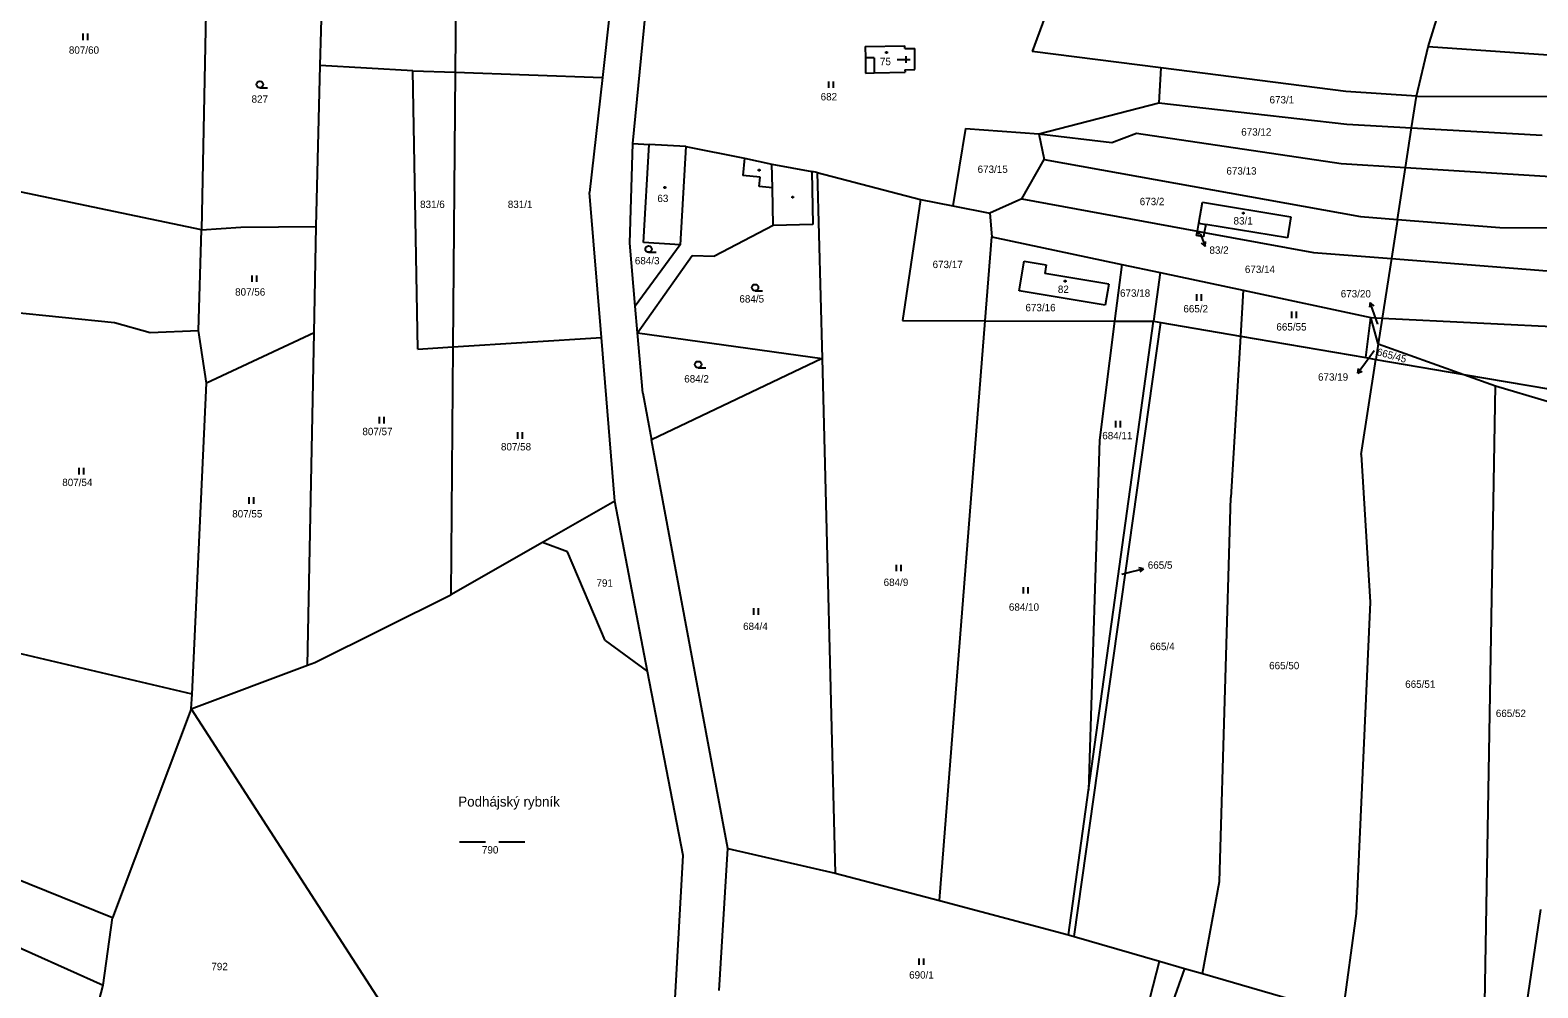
# Model space of a CAD drawing. Extents: x -791032 to -787751, y -1106872 to -1104403.
# Drawn here: x -789685.4 to -789337.7, y -1105820.2 to -1105599.2 of the extents above; entities that cross this region are included whole.
import ezdxf

# ---------------------------------------------------------------- set-up
doc = ezdxf.new("R2010")
doc.units = 0
for name, color, linetype in [('Komunikace', 7, 'Continuous'), ('Vrstva 1', 7, 'Continuous'), ('Vrstva 14', 7, 'Continuous'), ('Vrstva 15', 7, 'Continuous'), ('Vrstva 16', 7, 'Continuous'), ('Vrstva 2', 7, 'Continuous'), ('Vrstva 23', 7, 'Continuous'), ('Vrstva 25', 7, 'Continuous'), ('Vrstva 44', 7, 'Continuous')]:
    doc.layers.add(name, color=color, linetype=linetype)

msp = doc.modelspace()

# ---------------------------------------------------------------- linework, layer by layer
at = {"layer": 'Komunikace'}
for p, q in [((-789415.55, -1105646.15), (-789415.5, -1105646.28)), ((-789374.6, -1105667.04), (-789375.38, -1105664.84)), ((-789375.46, -1105673.21), (-789377.48, -1105675.95)), ((-789433.69, -1105724.75), (-789431.59, -1105724.22))]:
    msp.add_line(p, q, dxfattribs=at)
at = {"layer": 'Vrstva 1'}
for p, q in [((-789644.61, -1105581.09), (-789645.89, -1105645.25)), ((-789618.51, -1105607.33), (-789617.87, -1105582.98)), ((-789363.03, -1105603.06), (-789358.76, -1105589.25)), ((-789587.28, -1105591.81), (-789587.42, -1105608.89)), ((-789551.71, -1105594.77), (-789553.43, -1105610.08)), ((-789546.46, -1105625.33), (-789543.24, -1105592.17)), ((-789451.39, -1105596.16), (-789454.37, -1105604.11)), ((-789492.84, -1105602.94), (-789483.73, -1105602.81)), ((-789492.84, -1105602.94), (-789492.8, -1105605.59)), ((-789483.73, -1105603.41), (-789483.73, -1105602.81)), ((-789483.73, -1105603.41), (-789481.42, -1105603.44)), ((-789481.42, -1105608.24), (-789481.42, -1105603.44)), ((-789424.7, -1105607.88), (-789454.37, -1105604.11)), ((-789365.73, -1105614.42), (-789363.03, -1105603.06)), ((-789311.55, -1105606.53), (-789363.03, -1105603.06)), ((-789619.48, -1105644.48), (-789618.51, -1105607.33)), ((-789597.18, -1105608.55), (-789618.51, -1105607.33)), ((-789597.18, -1105608.55), (-789587.42, -1105608.89)), ((-789596.01, -1105672.81), (-789597.18, -1105608.55)), ((-789587.42, -1105608.89), (-789587.93, -1105672.29)), ((-789587.42, -1105608.89), (-789553.43, -1105610.08)), ((-789492.8, -1105605.59), (-789492.74, -1105609.09)), ((-789490.74, -1105609.05), (-789483.63, -1105608.9)), ((-789483.68, -1105608.31), (-789481.42, -1105608.24)), ((-789483.68, -1105608.31), (-789483.63, -1105608.9)), ((-789424.7, -1105607.88), (-789425.13, -1105615.94)), ((-789381.97, -1105613.32), (-789424.7, -1105607.88)), ((-789553.43, -1105610.08), (-789556.42, -1105636.65)), ((-789492.74, -1105609.09), (-789490.74, -1105609.05)), ((-789452.81, -1105623.11), (-789425.13, -1105615.94)), ((-789425.13, -1105615.94), (-789381.74, -1105620.9)), ((-789365.73, -1105614.42), (-789381.97, -1105613.32)), ((-789366.86, -1105621.73), (-789365.73, -1105614.42)), ((-789365.73, -1105614.42), (-789331.78, -1105614.45)), ((-789469.73, -1105621.91), (-789472.66, -1105639.71)), ((-789469.73, -1105621.91), (-789452.81, -1105623.11)), ((-789381.74, -1105620.9), (-789366.86, -1105621.73)), ((-789368.27, -1105630.86), (-789366.86, -1105621.73)), ((-789366.86, -1105621.73), (-789336.75, -1105623.41)), ((-789547.12, -1105648.3), (-789546.46, -1105625.33)), ((-789546.46, -1105625.33), (-789542.67, -1105625.55)), ((-789543.99, -1105648.21), (-789542.67, -1105625.55)), ((-789534.18, -1105626.04), (-789542.67, -1105625.55)), ((-789534.18, -1105626.04), (-789520.66, -1105628.73)), ((-789452.81, -1105623.11), (-789451.57, -1105629.03)), ((-789452.81, -1105623.11), (-789435.93, -1105625.13)), ((-789435.93, -1105625.13), (-789430.25, -1105622.93)), ((-789430.25, -1105622.93), (-789383.08, -1105629.95)), ((-789520.66, -1105628.73), (-789514.37, -1105630.09)), ((-789456.72, -1105638.1), (-789451.57, -1105629.03)), ((-789451.57, -1105629.03), (-789378.65, -1105642.16)), ((-789514.37, -1105630.09), (-789505.16, -1105631.82)), ((-789505.16, -1105631.82), (-789504.89, -1105644.03)), ((-789503.92, -1105632.05), (-789505.16, -1105631.82)), ((-789503.92, -1105632.05), (-789502.8, -1105674.96)), ((-789503.92, -1105632.05), (-789480.08, -1105638.25)), ((-789383.08, -1105629.95), (-789368.27, -1105630.86)), ((-789370.11, -1105642.84), (-789368.27, -1105630.86)), ((-789368.27, -1105630.86), (-789329.43, -1105633.26)), ((-789645.89, -1105645.25), (-789689.22, -1105636.15)), ((-789553.69, -1105670.1), (-789556.42, -1105636.65)), ((-789480.08, -1105638.25), (-789484.26, -1105666.21)), ((-789480.08, -1105638.25), (-789472.66, -1105639.71)), ((-789472.66, -1105639.71), (-789464.11, -1105641.39)), ((-789456.72, -1105638.1), (-789464.11, -1105641.39)), ((-789456.72, -1105638.1), (-789416.22, -1105645.56)), ((-789415.89, -1105643.74), (-789415.07, -1105638.91)), ((-789415.07, -1105638.91), (-789394.67, -1105642.28)), ((-789464.11, -1105641.39), (-789463.63, -1105646.85)), ((-789416.22, -1105645.56), (-789415.89, -1105643.74)), ((-789394.67, -1105642.28), (-789395.49, -1105647.11)), ((-789378.65, -1105642.16), (-789370.11, -1105642.84)), ((-789370.11, -1105642.84), (-789371.5, -1105651.89)), ((-789370.11, -1105642.84), (-789346.51, -1105644.71)), ((-789646.63, -1105668.52), (-789645.89, -1105645.25)), ((-789645.89, -1105645.25), (-789636.82, -1105644.66)), ((-789636.82, -1105644.66), (-789619.48, -1105644.48)), ((-789619.95, -1105669.06), (-789619.48, -1105644.48)), ((-789514.06, -1105644.23), (-789527.63, -1105651.37)), ((-789504.89, -1105644.03), (-789514.06, -1105644.23)), ((-789465.16, -1105666.26), (-789463.63, -1105646.85)), ((-789463.63, -1105646.85), (-789433.69, -1105653.23)), ((-789416.41, -1105646.59), (-789416.22, -1105645.56)), ((-789414.84, -1105646.88), (-789416.41, -1105646.59)), ((-789416.22, -1105645.56), (-789414.65, -1105645.85)), ((-789414.65, -1105645.85), (-789414.84, -1105646.88)), ((-789414.31, -1105644.03), (-789414.65, -1105645.85)), ((-789414.65, -1105645.85), (-789389.43, -1105650.49)), ((-789395.49, -1105647.11), (-789414.31, -1105644.03)), ((-789346.51, -1105644.71), (-789318.57, -1105644.88)), ((-789545.87, -1105662.9), (-789547.12, -1105648.3)), ((-789535.5, -1105648.7), (-789545.87, -1105662.9)), ((-789535.5, -1105648.7), (-789543.99, -1105648.21)), ((-789389.43, -1105650.49), (-789371.5, -1105651.89)), ((-789545.35, -1105669), (-789532.73, -1105651.15)), ((-789532.73, -1105651.15), (-789527.63, -1105651.37)), ((-789457.35, -1105659.34), (-789456.2, -1105652.48)), ((-789456.2, -1105652.48), (-789451.12, -1105653.34)), ((-789451.12, -1105653.34), (-789451.45, -1105655.31)), ((-789433.69, -1105653.23), (-789435.34, -1105666.34)), ((-789433.69, -1105653.23), (-789424.8, -1105655.13)), ((-789371.5, -1105651.89), (-789373.61, -1105665.61)), ((-789371.5, -1105651.89), (-789335.6, -1105654.69)), ((-789436.66, -1105657.8), (-789451.45, -1105655.31)), ((-789424.8, -1105655.13), (-789426.36, -1105666.37)), ((-789424.8, -1105655.13), (-789405.67, -1105659.21)), ((-789437.48, -1105662.68), (-789457.35, -1105659.34)), ((-789436.66, -1105657.8), (-789437.48, -1105662.68)), ((-789405.67, -1105659.21), (-789406.3, -1105669.8)), ((-789405.67, -1105659.21), (-789376.24, -1105665.48)), ((-789690.08, -1105664.2), (-789665.93, -1105666.61)), ((-789545.35, -1105669), (-789545.87, -1105662.9)), ((-789665.93, -1105666.61), (-789657.76, -1105668.96)), ((-789484.26, -1105666.21), (-789465.16, -1105666.26)), ((-789475.72, -1105800.08), (-789465.16, -1105666.26)), ((-789465.16, -1105666.26), (-789435.34, -1105666.34)), ((-789444.68, -1105808.33), (-789424.68, -1105666.66)), ((-789441.36, -1105774.6), (-789426.36, -1105666.37)), ((-789435.34, -1105666.34), (-789438.8, -1105693.8)), ((-789435.34, -1105666.34), (-789426.36, -1105666.37)), ((-789426.36, -1105666.37), (-789424.68, -1105666.66)), ((-789424.68, -1105666.66), (-789406.3, -1105669.8)), ((-789377.42, -1105674.75), (-789376.24, -1105665.48)), ((-789376.24, -1105665.48), (-789373.61, -1105665.61)), ((-789374.53, -1105671.57), (-789376.24, -1105665.48)), ((-789373.61, -1105665.61), (-789374.53, -1105671.57)), ((-789373.61, -1105665.61), (-789318.78, -1105668.36)), ((-789657.76, -1105668.96), (-789646.63, -1105668.52)), ((-789644.77, -1105680.65), (-789646.63, -1105668.52)), ((-789619.95, -1105669.06), (-789644.77, -1105680.65)), ((-789621.42, -1105745.7), (-789619.95, -1105669.06)), ((-789587.93, -1105672.29), (-789553.69, -1105670.1)), ((-789550.61, -1105707.88), (-789553.69, -1105670.1)), ((-789545.35, -1105669), (-789502.8, -1105674.96)), ((-789544.16, -1105682.98), (-789545.35, -1105669)), ((-789406.3, -1105669.8), (-789408.53, -1105707.03)), ((-789406.3, -1105669.8), (-789377.42, -1105674.75)), ((-789374.53, -1105671.57), (-789375.08, -1105675.15)), ((-789374.53, -1105671.57), (-789354.8, -1105678.63)), ((-789596.01, -1105672.81), (-789587.93, -1105672.29)), ((-789587.93, -1105672.29), (-789588.39, -1105729.48)), ((-789502.8, -1105674.96), (-789542.15, -1105693.74)), ((-789502.8, -1105674.96), (-789499.78, -1105793.72)), ((-789377.42, -1105674.75), (-789375.08, -1105675.15)), ((-789378.45, -1105697.1), (-789375.08, -1105675.15)), ((-789375.08, -1105675.15), (-789354.8, -1105678.63)), ((-789648.09, -1105752.4), (-789644.77, -1105680.65)), ((-789354.8, -1105678.63), (-789347.46, -1105681.25)), ((-789354.8, -1105678.63), (-789319.65, -1105684.65)), ((-789350.17, -1105836.83), (-789347.46, -1105681.25)), ((-789347.46, -1105681.25), (-789335.6, -1105684.78)), ((-789544.16, -1105682.98), (-789542.15, -1105693.74)), ((-789524.55, -1105788.02), (-789542.15, -1105693.74)), ((-789438.8, -1105693.8), (-789441.36, -1105774.6)), ((-789378.45, -1105697.1), (-789376.43, -1105731.19)), ((-789550.61, -1105707.88), (-789567.28, -1105717.41)), ((-789543.02, -1105747.21), (-789550.61, -1105707.88)), ((-789411.17, -1105795.63), (-789408.53, -1105707.03)), ((-789567.28, -1105717.41), (-789588.39, -1105729.48)), ((-789561.51, -1105719.56), (-789567.28, -1105717.41)), ((-789552.8, -1105740.04), (-789561.51, -1105719.56)), ((-789619.77, -1105745.08), (-789588.39, -1105729.48)), ((-789376.43, -1105731.19), (-789379.66, -1105803.05)), ((-789552.8, -1105740.04), (-789543.02, -1105747.21)), ((-789648.09, -1105752.4), (-789688.59, -1105742.87)), ((-789648.25, -1105755.79), (-789621.42, -1105745.7)), ((-789621.42, -1105745.7), (-789619.77, -1105745.08)), ((-789534.82, -1105789.69), (-789543.02, -1105747.21)), ((-789648.25, -1105755.79), (-789648.09, -1105752.4)), ((-789648.25, -1105755.79), (-789666.45, -1105804.08)), ((-789648.25, -1105755.79), (-789600.48, -1105829.85)), ((-789772.3, -1105773.18), (-789668.61, -1105819.59)), ((-789445.98, -1105807.95), (-789441.36, -1105774.6)), ((-789537.47, -1105836.39), (-789534.82, -1105789.69)), ((-789526.51, -1105820.83), (-789524.55, -1105788.02)), ((-789524.55, -1105788.02), (-789499.78, -1105793.72)), ((-789666.45, -1105804.08), (-789696.08, -1105792.03)), ((-789499.78, -1105793.72), (-789475.72, -1105800.08)), ((-789415.04, -1105816.93), (-789411.17, -1105795.63)), ((-789475.72, -1105800.08), (-789445.98, -1105807.95)), ((-789379.66, -1105803.05), (-789382.8, -1105826.28)), ((-789337.13, -1105802.12), (-789342.65, -1105839.26)), ((-789668.61, -1105819.59), (-789666.45, -1105804.08)), ((-789445.98, -1105807.95), (-789444.68, -1105808.33)), ((-789444.68, -1105808.33), (-789424.96, -1105814.05)), ((-789433.74, -1105847.82), (-789424.96, -1105814.05)), ((-789424.96, -1105814.05), (-789419.24, -1105815.71)), ((-789419.24, -1105815.71), (-789430.84, -1105848.7)), ((-789419.24, -1105815.71), (-789415.04, -1105816.93)), ((-789415.04, -1105816.93), (-789382.8, -1105826.28)), ((-789677.29, -1105852.93), (-789668.61, -1105819.59))]:
    msp.add_line(p, q, dxfattribs=at)
at = {"layer": 'Vrstva 16'}
for p, q in [((-789415.5, -1105646.28), (-789414.457, -1105649.092)), ((-789414.457, -1105649.092), (-789415.273, -1105648.329)), ((-789414.457, -1105649.092), (-789414.335, -1105647.981)), ((-789376.385, -1105662.013), (-789376.521, -1105663.123)), ((-789375.38, -1105664.84), (-789376.385, -1105662.013)), ((-789376.385, -1105662.013), (-789375.579, -1105662.788)), ((-789377.48, -1105675.95), (-789379.258, -1105678.365)), ((-789379.258, -1105678.365), (-789379.068, -1105677.263)), ((-789379.258, -1105678.365), (-789378.263, -1105677.856)), ((-789431.59, -1105724.22), (-789428.681, -1105723.482)), ((-789428.681, -1105723.482), (-789429.774, -1105723.243)), ((-789428.681, -1105723.482), (-789429.528, -1105724.213))]:
    msp.add_line(p, q, dxfattribs=at)
at = {"layer": 'Vrstva 2'}
for p, q in [((-789490.81, -1105605.56), (-789492.8, -1105605.59)), ((-789490.81, -1105605.56), (-789490.74, -1105609.05)), ((-789534.18, -1105626.04), (-789535.5, -1105648.7)), ((-789520.66, -1105628.73), (-789521.07, -1105632.71)), ((-789517.09, -1105633.12), (-789521.07, -1105632.71)), ((-789517.31, -1105635.23), (-789517.09, -1105633.12)), ((-789514.25, -1105635.55), (-789514.37, -1105630.09)), ((-789514.25, -1105635.55), (-789517.31, -1105635.23)), ((-789514.06, -1105644.23), (-789514.25, -1105635.55)), ((-789415.89, -1105643.74), (-789414.31, -1105644.03))]:
    msp.add_line(p, q, dxfattribs=at)
at = {"layer": 'Vrstva 23'}
for p, q in [((-789673.2, -1105601.46), (-789673.2, -1105599.96)), ((-789672.2, -1105599.96), (-789672.2, -1105601.46)), ((-789483.505, -1105605.146), (-789483.494, -1105606.746)), ((-789485.5, -1105605.96), (-789482.5, -1105605.94)), ((-789632.46, -1105612.45), (-789630.71, -1105612.45)), ((-789501.23, -1105612.51), (-789501.23, -1105611.01)), ((-789500.23, -1105611.01), (-789500.23, -1105612.51)), ((-789542.79, -1105650.45), (-789541.04, -1105650.45)), ((-789634.24, -1105657.29), (-789634.24, -1105655.79)), ((-789633.24, -1105655.79), (-789633.24, -1105657.29)), ((-789518.25, -1105659.34), (-789516.5, -1105659.34)), ((-789416.34, -1105661.62), (-789416.34, -1105660.12)), ((-789415.34, -1105660.12), (-789415.34, -1105661.62)), ((-789394.43, -1105665.61), (-789394.43, -1105664.11)), ((-789393.43, -1105664.11), (-789393.43, -1105665.61)), ((-789531.36, -1105677.11), (-789529.61, -1105677.11)), ((-789604.85, -1105689.95), (-789604.85, -1105688.45)), ((-789603.85, -1105688.45), (-789603.85, -1105689.95)), ((-789572.94, -1105693.47), (-789572.94, -1105691.97)), ((-789571.94, -1105691.97), (-789571.94, -1105693.47)), ((-789435.04, -1105690.85), (-789435.04, -1105689.35)), ((-789434.04, -1105689.35), (-789434.04, -1105690.85)), ((-789674.12, -1105701.7), (-789674.12, -1105700.2)), ((-789673.12, -1105700.2), (-789673.12, -1105701.7)), ((-789634.89, -1105708.49), (-789634.89, -1105706.99)), ((-789633.89, -1105706.99), (-789633.89, -1105708.49)), ((-789485.59, -1105724.05), (-789485.59, -1105722.55)), ((-789484.59, -1105722.55), (-789484.59, -1105724.05)), ((-789456.33, -1105729.23), (-789456.33, -1105727.73)), ((-789455.33, -1105727.73), (-789455.33, -1105729.23)), ((-789518.56, -1105734.1), (-789518.56, -1105732.6)), ((-789517.56, -1105732.6), (-789517.56, -1105734.1)), ((-789586.37, -1105786.5), (-789580.37, -1105786.5)), ((-789577.37, -1105786.5), (-789571.37, -1105786.5)), ((-789480.42, -1105814.91), (-789480.42, -1105813.41)), ((-789479.42, -1105813.41), (-789479.42, -1105814.91))]:
    msp.add_line(p, q, dxfattribs=at)
for centre in [(-789632.46, -1105611.7), (-789542.79, -1105649.7), (-789518.25, -1105658.59), (-789531.36, -1105676.36)]:
    msp.add_circle(centre, 0.75, dxfattribs=at)
at = {"layer": 'Vrstva 25'}
for p, q in [((-789488.07, -1105604.17), (-789487.77, -1105604.17)), ((-789488.07, -1105604.47), (-789488.07, -1105604.17)), ((-789487.77, -1105604.47), (-789488.07, -1105604.47)), ((-789487.77, -1105604.17), (-789487.77, -1105604.47)), ((-789517.48, -1105631.36), (-789517.18, -1105631.36)), ((-789517.48, -1105631.66), (-789517.48, -1105631.36)), ((-789517.18, -1105631.66), (-789517.48, -1105631.66)), ((-789517.18, -1105631.36), (-789517.18, -1105631.66)), ((-789539.21, -1105635.36), (-789538.91, -1105635.36)), ((-789539.21, -1105635.66), (-789539.21, -1105635.36)), ((-789538.91, -1105635.66), (-789539.21, -1105635.66)), ((-789538.91, -1105635.36), (-789538.91, -1105635.66)), ((-789509.72, -1105637.59), (-789509.42, -1105637.59)), ((-789509.72, -1105637.89), (-789509.72, -1105637.59)), ((-789509.42, -1105637.89), (-789509.72, -1105637.89)), ((-789509.42, -1105637.59), (-789509.42, -1105637.89)), ((-789405.79, -1105641.26), (-789405.49, -1105641.26)), ((-789405.79, -1105641.56), (-789405.79, -1105641.26)), ((-789405.49, -1105641.56), (-789405.79, -1105641.56)), ((-789405.49, -1105641.26), (-789405.49, -1105641.56)), ((-789416.067, -1105645.983), (-789415.866, -1105645.983)), ((-789416.067, -1105646.184), (-789416.067, -1105645.983)), ((-789415.866, -1105646.184), (-789416.067, -1105646.184)), ((-789415.866, -1105645.983), (-789415.866, -1105646.184)), ((-789446.89, -1105656.95), (-789446.59, -1105656.95)), ((-789446.89, -1105657.25), (-789446.89, -1105656.95)), ((-789446.59, -1105657.25), (-789446.89, -1105657.25)), ((-789446.59, -1105656.95), (-789446.59, -1105657.25))]:
    msp.add_line(p, q, dxfattribs=at)

# ---------------------------------------------------------------- texts
at = {"layer": 'Vrstva 14'}
for s, height, p in [('807/60', 1.7, (-789676.485, -1105604.62)), ('827', 1.7, (-789634.353, -1105615.93)), ('682', 1.7, (-789503.116, -1105615.39)), ('673/1', 1.7, (-789399.6, -1105616.09)), ('673/12', 1.7, (-789406.13, -1105623.52)), ('673/15', 1.7, (-789466.926, -1105632.12)), ('673/13', 1.7, (-789409.55, -1105632.51)), ('831/6', 1.7, (-789595.493, -1105640.22)), ('831/1', 1.7, (-789575.266, -1105640.22)), ('673/2', 1.7, (-789429.536, -1105639.57)), ('684/3', 1.7, (-789545.966, -1105653.22)), ('673/17', 1.7, (-789477.306, -1105654.09)), ('673/14', 1.7, (-789405.286, -1105655.22)), ('807/56', 1.7, (-789638.152, -1105660.44)), ('684/5', 1.7, (-789521.852, -1105662.04)), ('673/18', 1.7, (-789434.08, -1105660.71)), ('673/16', 1.7, (-789455.89, -1105664.05)), ('665/2', 1.7, (-789419.466, -1105664.32)), ('665/55', 1.7, (-789398.019, -1105668.5)), ('673/20', 0.1, (-789374.852, -1105667.04)), ('673/19', 0.1, (-789375.7, -1105673.21)), ('684/2', 1.7, (-789534.575, -1105680.5)), ('807/57', 1.7, (-789608.798, -1105692.65)), ('684/11', 1.7, (-789438.172, -1105693.6)), ('807/58', 1.7, (-789576.842, -1105696.17)), ('807/54', 1.7, (-789678.008, -1105704.4)), ('807/55', 1.7, (-789638.818, -1105711.64)), ('791', 1.7, (-789554.817, -1105727.62)), ('684/9', 1.7, (-789488.596, -1105727.45)), ('665/5', 0.1, (-789433.899, -1105724.75)), ('684/10', 1.7, (-789459.708, -1105733.17)), ('684/4', 1.7, (-789521.001, -1105737.62)), ('665/4', 1.7, (-789427.172, -1105742.26)), ('665/50', 1.7, (-789399.692, -1105746.67)), ('665/51', 1.7, (-789368.316, -1105750.96)), ('665/52', 1.7, (-789347.412, -1105757.7)), ('790', 1.7, (-789581.232, -1105789.2)), ('792', 1.7, (-789643.623, -1105816.13)), ('690/1', 1.7, (-789482.712, -1105818.07))]:
    msp.add_text(s, height=height, dxfattribs=at).set_placement(p)
msp.add_text('665/45', height=1.7, rotation=344.98161, dxfattribs=at).set_placement((-789374.992, -1105674.176))
at = {"layer": 'Vrstva 15'}
for s, height, p in [('75', 1.7, (-789489.44, -1105607.26)), ('63', 1.7, (-789540.767, -1105638.85)), ('83/1', 1.7, (-789407.903, -1105644.03)), ('83/2', 0.1, (-789415.71, -1105646.15)), ('82', 1.7, (-789448.416, -1105659.83))]:
    msp.add_text(s, height=height, dxfattribs=at).set_placement(p)
at = {"layer": 'Vrstva 16'}
for s, p in [('83/2', (-789413.46, -1105650.79)), ('673/20', (-789383.181, -1105660.86)), ('673/19', (-789388.42, -1105680.07)), ('665/5', (-789427.68, -1105723.48))]:
    msp.add_text(s, height=1.7, dxfattribs=at).set_placement(p)
at = {"layer": 'Vrstva 44'}
msp.add_text('Podhájský rybník', height=2.3, dxfattribs=at).set_placement((-789586.68, -1105778.37))

doc.saveas('drawing.dxf')
